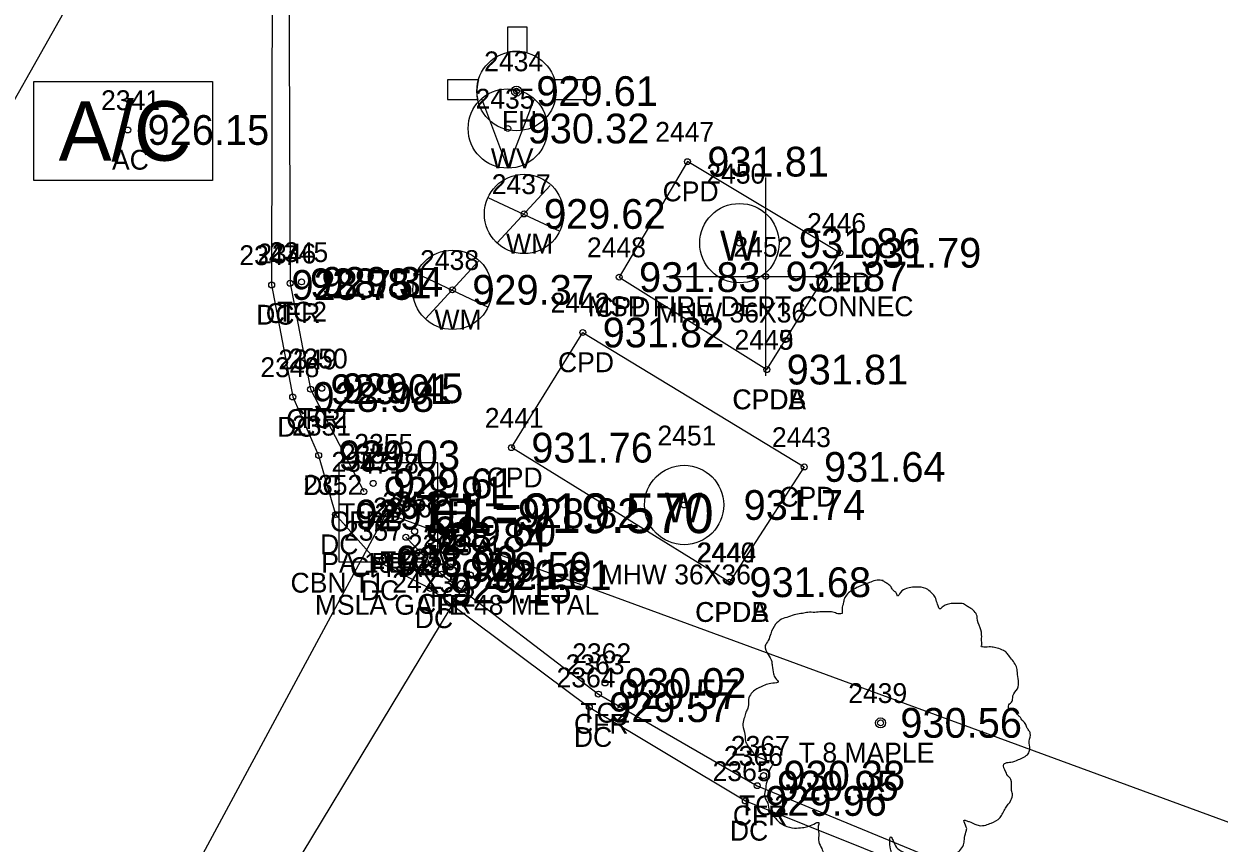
# Model space of a CAD drawing. Extents: x 1575382 to 1578175, y 1099175 to 1101955.
# Drawn here: x 1576768.2 to 1576828.4, y 1100126.4 to 1100167.7 of the extents above; entities that cross this region are included whole.
import ezdxf

# ---------------------------------------------------------------- set-up
doc = ezdxf.new("R2010")
doc.units = 0
for name, color, linetype in [('RD_EX_BldgApp', 7, 'Continuous'), ('RD_EX_BldgApp_txCode', 7, 'Continuous'), ('RD_EX_Conc', 7, 'Continuous'), ('RD_EX_Conc_txCode', 7, 'Continuous'), ('RD_EX_DR_Inlet', 7, 'Continuous'), ('RD_EX_DR_Inlet_txCode', 7, 'Continuous'), ('RD_EX_DR_Pipe', 7, 'Continuous'), ('RD_EX_DR_Pipe_txCode', 7, 'Continuous'), ('RD_EX_Misc', 7, 'Continuous'), ('RD_EX_Misc_txCode', 7, 'Continuous'), ('RD_EX_Road', 7, 'Continuous'), ('RD_EX_SU_H2O', 7, 'Continuous'), ('RD_EX_TX_BldgApp_ELEV', 7, 'Continuous'), ('RD_EX_TX_Conc_ELEV', 7, 'Continuous'), ('RD_EX_TX_DR_Inlet_ELEV', 7, 'Continuous'), ('RD_EX_TX_Misc_ELEV', 7, 'Continuous'), ('RD_EX_TX_UT_ELEV', 7, 'Continuous'), ('RD_EX_TX_VEG_ELEV', 7, 'Continuous'), ('RD_EX_UT', 7, 'Continuous'), ('RD_EX_UT_txCode', 7, 'Continuous'), ('RD_EX_VEG', 7, 'Continuous'), ('RD_EX_VEG_txCode', 7, 'Continuous'), ('RD_HC_Data', 7, 'Continuous'), ('RD_SMD_Locator', 7, 'Continuous'), ('RD_TX_Pipe_ElevEX', 7, 'Continuous')]:
    doc.layers.add(name, color=color, linetype=linetype)

msp = doc.modelspace()

# ---------------------------------------------------------------- linework, layer by layer
at = {"layer": 'RD_EX_BldgApp'}
msp.add_lwpolyline([(1576768.656, 1100159.831), (1576768.656, 1100164.831), (1576777.656, 1100164.831), (1576777.656, 1100159.831)], close=True, dxfattribs=at)
at = {"layer": 'RD_EX_Conc'}
for points in [[(1576785.777, 1100195.961), (1576786.17, 1100195.752), (1576783.397, 1100187.603), (1576781.942, 1100181.747), (1576781.056, 1100176.612), (1576780.677, 1100170.531), (1576780.648, 1100154.572), (1576781.71, 1100148.925), (1576783.019, 1100145.98), (1576783.874, 1100142.998), (1576785.927, 1100140.682), (1576788.648, 1100139.275), (1576796.673, 1100133.29), (1576804.546, 1100128.565), (1576819.43, 1100122.601)], [(1576782.012, 1100176.69), (1576781.508, 1100170.553), (1576781.58, 1100154.655), (1576782.614, 1100149.316), (1576785.295, 1100144.157)], [(1576805.627, 1100150.306), (1576809.311, 1100156.194), (1576801.625, 1100160.787), (1576798.181, 1100154.967), (1576805.627, 1100150.306)], [(1576803.749, 1100139.589), (1576792.746, 1100146.371), (1576796.345, 1100152.176), (1576807.513, 1100145.4), (1576803.749, 1100139.589)], [(1576787.42, 1100141.854), (1576789.211, 1100139.996), (1576797.129, 1100133.951), (1576805.141, 1100129.335), (1576819.688, 1100123.321)]]:
    msp.add_lwpolyline(points, dxfattribs=at)
at = {"layer": 'RD_EX_DR_Inlet'}
msp.add_line((1576789.035, 1100140.609), (1576789.035, 1100145.609), dxfattribs=at)
msp.add_lwpolyline([(1576789.035, 1100140.609), (1576789.035, 1100145.609), (1576784.035, 1100145.609), (1576784.035, 1100140.609)], close=True, dxfattribs=at)
at = {"layer": 'RD_EX_DR_Pipe'}
msp.add_lwpolyline([(1576756.712, 1100087.957), (1576786.445, 1100143.064), (1576786.445, 1100143.064), (1576927.309, 1100091.425)], dxfattribs=at)
at = {"layer": 'RD_EX_Misc'}
for p, q in [((1576805.573, 1100149.996), (1576805.573, 1100159.996)), ((1576800.573, 1100154.996), (1576810.573, 1100154.996)), ((1576790.668, 1100139.95), (1576773.845, 1100112.125))]:
    msp.add_line(p, q, dxfattribs=at)
at = {"layer": 'RD_EX_Road'}
msp.add_lwpolyline([(1576663.307, 1099979.534), (1576687.432, 1100021.526), (1576712.032, 1100065.104), (1576738.416, 1100112.144), (1576760.611, 1100151.412), (1576785.777, 1100195.961), (1576800.589, 1100221.872), (1576817.543, 1100252.084), (1576858.248, 1100324.631), (1576880.454, 1100364.005), (1576883.5, 1100369.448), (1576896.98, 1100397.709)], dxfattribs=at)
at = {"layer": 'RD_EX_SU_H2O'}
for centre in [(1576804.245, 1100156.678), (1576801.455, 1100143.482)]:
    msp.add_circle(centre, 2, dxfattribs=at)
at = {"layer": 'RD_EX_UT'}
for p, q in [((1576792.541, 1100167.563), (1576792.541, 1100166.289)), ((1576793.541, 1100167.563), (1576792.541, 1100167.563)), ((1576793.541, 1100166.266), (1576793.541, 1100167.563)), ((1576791.082, 1100164.915), (1576789.524, 1100164.915)), ((1576789.524, 1100164.915), (1576789.524, 1100163.915)), ((1576796.524, 1100164.915), (1576794.914, 1100164.915)), ((1576796.524, 1100163.915), (1576796.524, 1100164.915)), ((1576789.524, 1100163.915), (1576791.044, 1100163.915)), ((1576792.562, 1100160.465), (1576791.259, 1100163.948)), ((1576792.562, 1100160.465), (1576793.885, 1100163.911)), ((1576794.952, 1100163.915), (1576796.524, 1100163.915)), ((1576792.03, 1100156.693), (1576794.697, 1100159.589)), ((1576791.548, 1100158.988), (1576795.179, 1100157.275)), ((1576788.416, 1100152.868), (1576791.084, 1100155.764)), ((1576787.935, 1100155.163), (1576791.566, 1100153.45))]:
    msp.add_line(p, q, dxfattribs=at)
for centre, radius in [((1576792.998, 1100164.342), 2), ((1576792.562, 1100162.458), 2), ((1576792.998, 1100164.342), 0.25), ((1576793.382, 1100158.151), 2), ((1576789.768, 1100154.326), 2)]:
    msp.add_circle(centre, radius, dxfattribs=at)
for start, end in [(74.24553, 103.21276), (163.3387, 192.31502), (347.68498, 16.6613)]:
    msp.add_arc((1576792.998, 1100164.342), 2, start, end, dxfattribs=at)
at = {"layer": 'RD_EX_VEG'}
for centre, radius in [((1576811.362, 1100132.501), 0.25), ((1576811.35, 1100132.482), 0.0001)]:
    msp.add_circle(centre, radius, dxfattribs=at)
for points in [[(1576811.494, 1100139.669), (1576811.194, 1100139.694), (1576810.869, 1100139.594), (1576810.619, 1100139.494), (1576810.395, 1100139.419), (1576810.17, 1100139.319), (1576809.87, 1100139.144), (1576809.645, 1100138.944), (1576809.52, 1100138.694), (1576809.47, 1100138.469), (1576809.42, 1100138.194), (1576809.42, 1100138.019), (1576809.295, 1100137.994), (1576809.145, 1100138.019), (1576808.895, 1100138.094), (1576808.645, 1100138.094), (1576808.395, 1100138.094), (1576808.046, 1100138.069), (1576807.696, 1100138.069), (1576807.421, 1100138.019), (1576807.096, 1100137.969), (1576806.721, 1100137.844), (1576806.371, 1100137.719), (1576806.071, 1100137.469), (1576805.822, 1100136.995), (1576805.697, 1100136.645), (1576805.547, 1100136.395), (1576805.697, 1100135.945), (1576805.872, 1100135.595), (1576805.896, 1100135.395), (1576805.971, 1100134.971), (1576806.071, 1100134.746), (1576806.196, 1100134.546), (1576806.121, 1100134.521), (1576805.747, 1100134.471), (1576805.447, 1100134.371), (1576805.022, 1100134.146), (1576804.797, 1100133.921), (1576804.697, 1100133.596), (1576804.672, 1100133.246), (1576804.572, 1100133.046), (1576804.497, 1100132.772), (1576804.472, 1100132.697), (1576804.422, 1100132.372), (1576804.522, 1100131.922), (1576804.547, 1100131.572), (1576804.672, 1100131.347), (1576804.822, 1100131.172), (1576804.997, 1100130.922), (1576805.397, 1100130.697), (1576805.722, 1100130.597), (1576805.921, 1100130.573), (1576805.747, 1100130.073), (1576805.697, 1100129.723), (1576805.572, 1100129.323), (1576805.572, 1100129.248), (1576805.522, 1100128.773), (1576805.672, 1100128.448), (1576805.747, 1100128.074), (1576805.921, 1100127.849), (1576806.196, 1100127.549), (1576806.521, 1100127.324), (1576807.021, 1100127.199), (1576807.421, 1100127.224), (1576807.996, 1100127.399), (1576808.245, 1100127.474), (1576808.22, 1100127.299), (1576808.245, 1100126.924), (1576808.245, 1100126.499), (1576808.395, 1100126.174), (1576808.495, 1100125.9), (1576808.645, 1100125.65), (1576808.97, 1100125.425), (1576809.37, 1100125.35), (1576809.795, 1100125.2), (1576810.245, 1100125.125), (1576810.744, 1100125.1), (1576811.344, 1100125.25), (1576811.619, 1100125.375), (1576811.719, 1100125.55), (1576811.919, 1100125.925), (1576811.869, 1100126.149), (1576811.894, 1100126.749), (1576811.994, 1100126.574), (1576812.169, 1100126.224), (1576812.669, 1100125.925), (1576813.068, 1100125.75), (1576813.543, 1100125.6), (1576813.843, 1100125.525), (1576814.318, 1100125.6), (1576814.693, 1100125.675), (1576815.067, 1100125.8), (1576815.367, 1100126.074), (1576815.542, 1100126.349), (1576815.592, 1100126.624), (1576815.667, 1100126.999), (1576815.717, 1100127.174)], [(1576815.717, 1100127.174), (1576815.642, 1100127.349), (1576815.592, 1100127.599), (1576815.667, 1100127.574), (1576815.842, 1100127.524), (1576816.117, 1100127.399), (1576816.342, 1100127.324), (1576816.667, 1100127.349), (1576816.942, 1100127.449), (1576817.391, 1100127.724), (1576817.666, 1100128.199), (1576817.941, 1100128.598), (1576818.016, 1100128.923), (1576817.966, 1100129.148), (1576817.941, 1100129.648), (1576817.741, 1100129.898), (1576817.691, 1100130.023), (1576817.591, 1100130.423), (1576817.666, 1100130.473), (1576817.941, 1100130.523), (1576818.316, 1100130.647), (1576818.591, 1100130.772), (1576818.816, 1100130.947), (1576818.891, 1100131.172), (1576818.866, 1100131.572), (1576818.916, 1100131.972), (1576818.841, 1100132.122), (1576818.741, 1100132.272), (1576818.666, 1100132.472), (1576818.516, 1100132.622), (1576818.416, 1100132.772), (1576818.316, 1100132.871), (1576818.191, 1100133.021), (1576818.016, 1100133.146), (1576817.866, 1100133.196), (1576817.816, 1100133.346), (1576817.966, 1100133.546), (1576818.016, 1100133.646), (1576818.041, 1100133.871), (1576818.266, 1100134.221), (1576818.316, 1100134.621), (1576818.266, 1100135.046), (1576818.216, 1100135.32), (1576818.066, 1100135.595), (1576817.866, 1100135.845), (1576817.741, 1100136.02), (1576817.566, 1100136.145), (1576817.242, 1100136.27), (1576816.992, 1100136.32), (1576816.642, 1100136.32), (1576816.442, 1100136.37), (1576816.467, 1100136.42), (1576816.467, 1100136.57), (1576816.467, 1100136.845), (1576816.392, 1100137.295), (1576816.242, 1100137.794), (1576816.242, 1100137.819), (1576816.142, 1100138.069), (1576815.917, 1100138.269), (1576815.742, 1100138.369), (1576815.542, 1100138.494), (1576815.292, 1100138.519), (1576814.993, 1100138.519), (1576814.718, 1100138.469), (1576814.518, 1100138.369), (1576814.343, 1100138.244), (1576814.268, 1100138.394), (1576814.168, 1100138.694), (1576814.118, 1100138.844), (1576813.968, 1100139.019), (1576813.743, 1100139.219), (1576813.293, 1100139.344), (1576812.669, 1100139.269), (1576812.369, 1100139.069), (1576812.219, 1100138.894), (1576812.169, 1100139.019), (1576811.969, 1100139.219), (1576811.869, 1100139.394), (1576811.694, 1100139.519), (1576811.544, 1100139.619), (1576811.444, 1100139.669)]]:
    msp.add_spline(points, degree=3, dxfattribs=at)
at = {"layer": 'RD_SMD_Locator'}
for centre, radius in [((1576792.998, 1100164.342), 0.15), ((1576792.562, 1100162.458), 0.15), ((1576773.39, 1100162.383), 0.15), ((1576801.625, 1100160.787), 0.15), ((1576793.382, 1100158.151), 0.15), ((1576804.245, 1100156.678), 0.15), ((1576809.311, 1100156.194), 0.15), ((1576780.648, 1100154.572), 0.15), ((1576781.58, 1100154.655), 0.15), ((1576782.157, 1100154.726), 0.15), ((1576798.181, 1100154.967), 0.15), ((1576805.573, 1100154.996), 0.15), ((1576789.768, 1100154.326), 0.15), ((1576796.345, 1100152.176), 0.15), ((1576805.627, 1100150.306), 0.15), ((1576805.627, 1100150.306), 0.15), ((1576782.614, 1100149.316), 0.15), ((1576783.179, 1100149.364), 0.15), ((1576781.71, 1100148.925), 0.15), ((1576792.746, 1100146.371), 0.15), ((1576783.019, 1100145.98), 0.15), ((1576807.513, 1100145.4), 0.15), ((1576785.771, 1100144.572), 0.15), ((1576785.295, 1100144.157), 0.15), ((1576786.445, 1100143.064), 0.2), ((1576786.445, 1100143.064), 0.2), ((1576801.455, 1100143.482), 0.15), ((1576783.874, 1100142.998), 0.15), ((1576786.445, 1100143.064), 0.15), ((1576787.859, 1100142.151), 0.15), ((1576787.42, 1100141.854), 0.15), ((1576785.927, 1100140.682), 0.15), ((1576789.652, 1100140.36), 0.15), ((1576789.211, 1100139.996), 0.15), ((1576790.668, 1100139.95), 0.15), ((1576803.749, 1100139.589), 0.15), ((1576803.749, 1100139.589), 0.15), ((1576788.648, 1100139.275), 0.15), ((1576797.464, 1100134.51), 0.15), ((1576797.129, 1100133.951), 0.15), ((1576796.673, 1100133.29), 0.15), ((1576811.362, 1100132.501), 0.15), ((1576805.141, 1100129.335), 0.15), ((1576805.466, 1100129.841), 0.15), ((1576804.546, 1100128.565), 0.15)]:
    msp.add_circle(centre, radius, dxfattribs=at)

# ---------------------------------------------------------------- texts
at = {"layer": 'RD_EX_BldgApp'}
msp.add_text('A/C', height=3, dxfattribs=at).set_placement((1576769.902, 1100160.835))
at = {"layer": 'RD_EX_BldgApp_txCode'}
for s, p in [('2341', (1576772.044, 1100163.383)), ('AC', (1576772.595, 1100160.383))]:
    msp.add_text(s, height=1, dxfattribs=at).set_placement(p)
at = {"layer": 'RD_EX_Conc_txCode'}
for s, p in [('2447', (1576799.995, 1100161.787)), ('CPD', (1576800.373, 1100158.787)), ('2446', (1576807.658, 1100157.194)), ('2347', (1576779.018, 1100155.572)), ('2346', (1576779.926, 1100155.655)), ('2345', (1576780.527, 1100155.726)), ('2448', (1576796.551, 1100155.967)), ('CPD', (1576808.059, 1100154.194)), ('2442', (1576794.715, 1100153.176)), ('DC', (1576779.868, 1100152.572)), ('CFR', (1576780.351, 1100152.655)), ('TC2', (1576780.913, 1100152.726)), ('CPD', (1576796.929, 1100152.967)), ('2445', (1576803.997, 1100151.306)), ('2449', (1576803.997, 1100151.306)), ('2349', (1576780.984, 1100150.316)), ('2350', (1576781.51, 1100150.364)), ('CPD', (1576795.093, 1100150.176)), ('2348', (1576780.08, 1100149.925)), ('CPDA', (1576803.887, 1100148.306)), ('CPDB', (1576803.902, 1100148.306)), ('CFR', (1576781.386, 1100147.316)), ('TC2', (1576781.935, 1100147.364)), ('2441', (1576791.399, 1100147.371)), ('DC', (1576780.931, 1100146.925)), ('2351', (1576781.673, 1100146.98)), ('2443', (1576805.883, 1100146.4)), ('2354', (1576784.141, 1100145.572)), ('2353', (1576783.665, 1100145.157)), ('CPD', (1576791.494, 1100144.371)), ('2352', (1576782.244, 1100143.998)), ('DC', (1576782.24, 1100143.98)), ('2356', (1576785.766, 1100142.854)), ('2358', (1576786.229, 1100143.151)), ('CPD', (1576806.261, 1100143.4)), ('TC2B', (1576784.054, 1100142.572)), ('CFRB', (1576783.594, 1100142.157)), ('2357', (1576784.297, 1100141.682)), ('2361', (1576788.282, 1100141.36)), ('DC', (1576783.094, 1100140.998)), ('2360', (1576787.518, 1100140.996)), ('2440', (1576802.08, 1100140.589)), ('2444', (1576802.119, 1100140.589)), ('CFRA 18', (1576784.601, 1100139.854)), ('TC2A', (1576786.126, 1100140.151)), ('2359', (1576787.018, 1100140.275)), ('DC', (1576785.147, 1100138.682)), ('TC2', (1576788.408, 1100138.36)), ('CFR', (1576787.982, 1100137.996)), ('CPDA', (1576802.009, 1100137.589)), ('CPDB', (1576802.024, 1100137.589)), ('DC', (1576787.869, 1100137.275)), ('2362', (1576795.81, 1100135.51)), ('2363', (1576795.476, 1100134.951)), ('2364', (1576795.02, 1100134.29)), ('TC2', (1576796.22, 1100132.51)), ('CFR', (1576795.901, 1100131.951)), ('DC', (1576795.894, 1100131.29)), ('2367', (1576803.813, 1100130.841)), ('2366', (1576803.463, 1100130.335)), ('2365', (1576802.893, 1100129.565)), ('TC2', (1576804.222, 1100127.841)), ('CFR', (1576803.912, 1100127.335)), ('DC', (1576803.767, 1100126.565))]:
    msp.add_text(s, height=1, dxfattribs=at).set_placement(p)
at = {"layer": 'RD_EX_DR_Inlet_txCode'}
for s, p in [('2355', (1576784.815, 1100146.064)), ('CBN T1 24X36', (1576781.602, 1100139.064))]:
    msp.add_text(s, height=1, dxfattribs=at).set_placement(p)
at = {"layer": 'RD_EX_DR_Pipe_txCode'}
for s, p in [('4718', (1576785.098, 1100145.064)), ('4717', (1576785.098, 1100145.064)), ('PA 18 RC', (1576783.153, 1100140.064)), ('PB', (1576785.665, 1100140.064))]:
    msp.add_text(s, height=1, dxfattribs=at).set_placement(p)
at = {"layer": 'RD_EX_Misc_txCode'}
for s, p in [('2452', (1576803.943, 1100155.996)), ('MSP FIRE DEPT CONNEC', (1576796.604, 1100152.996)), ('2371', (1576789.281, 1100140.95)), ('MSLA GATE 48 METAL', (1576782.829, 1100137.95))]:
    msp.add_text(s, height=1, dxfattribs=at).set_placement(p)
at = {"layer": 'RD_EX_SU_H2O'}
for p in [(1576803.262, 1100155.802), (1576800.473, 1100142.606)]:
    msp.add_text('W', height=1.5, dxfattribs=at).set_placement(p)
at = {"layer": 'RD_EX_TX_BldgApp_ELEV'}
msp.add_text('926.15', height=1.5, dxfattribs=at).set_placement((1576774.39, 1100161.633))
at = {"layer": 'RD_EX_TX_Conc_ELEV'}
for s, p in [('931.81', (1576802.625, 1100160.037)), ('931.79', (1576810.311, 1100155.444)), ('928.75', (1576781.648, 1100153.822)), ('928.81', (1576782.58, 1100153.905)), ('929.34', (1576783.157, 1100153.976)), ('931.83', (1576799.181, 1100154.217)), ('931.82', (1576797.345, 1100151.426)), ('931.81', (1576806.627, 1100149.556)), ('931.81', (1576806.627, 1100149.556)), ('929.01', (1576783.614, 1100148.566)), ('929.45', (1576784.179, 1100148.614)), ('928.98', (1576782.71, 1100148.175)), ('931.76', (1576793.746, 1100145.621)), ('929.03', (1576784.019, 1100145.23)), ('931.64', (1576808.513, 1100144.65)), ('929.61', (1576786.771, 1100143.822)), ('928.91', (1576786.295, 1100143.407)), ('929.07', (1576784.874, 1100142.248)), ('929.60', (1576788.859, 1100141.401)), ('928.84', (1576788.42, 1100141.104)), ('928.99', (1576786.927, 1100139.932)), ('929.59', (1576790.652, 1100139.61)), ('929.11', (1576790.211, 1100139.246)), ('931.68', (1576804.749, 1100138.839)), ('931.68', (1576804.749, 1100138.839)), ('929.15', (1576789.648, 1100138.525)), ('930.02', (1576798.464, 1100133.76)), ('929.57', (1576798.129, 1100133.201)), ('929.57', (1576797.673, 1100132.54)), ('930.38', (1576806.466, 1100129.091)), ('929.95', (1576806.141, 1100128.585)), ('929.96', (1576805.546, 1100127.815))]:
    msp.add_text(s, height=1.5, dxfattribs=at).set_placement(p)
at = {"layer": 'RD_EX_TX_DR_Inlet_ELEV'}
msp.add_text('EL=928.82', height=1.5, dxfattribs=at).set_placement((1576789.445, 1100142.314))
at = {"layer": 'RD_EX_TX_Misc_ELEV'}
for s, p in [('931.87', (1576806.573, 1100154.246)), ('929.61', (1576791.668, 1100139.2))]:
    msp.add_text(s, height=1.5, dxfattribs=at).set_placement(p)
at = {"layer": 'RD_EX_TX_UT_ELEV'}
for s, p in [('929.61', (1576793.998, 1100163.592)), ('930.32', (1576793.562, 1100161.708)), ('929.62', (1576794.382, 1100157.401)), ('931.86', (1576807.245, 1100155.928)), ('929.37', (1576790.768, 1100153.576)), ('931.74', (1576804.455, 1100142.732))]:
    msp.add_text(s, height=1.5, dxfattribs=at).set_placement(p)
at = {"layer": 'RD_EX_TX_VEG_ELEV'}
msp.add_text('930.56', height=1.5, dxfattribs=at).set_placement((1576812.362, 1100131.751))
at = {"layer": 'RD_EX_UT_txCode'}
for s, p in [('2434', (1576791.368, 1100165.342)), ('2435', (1576790.932, 1100163.458)), ('FH', (1576792.266, 1100162.342)), ('WV', (1576791.704, 1100160.458)), ('2437', (1576791.752, 1100159.151)), ('2450', (1576802.575, 1100159.678)), ('WM', (1576792.476, 1100156.151)), ('2438', (1576788.138, 1100155.326)), ('MHW 36X36', (1576800.032, 1100152.678)), ('WM', (1576788.863, 1100152.326)), ('2451', (1576800.109, 1100146.482)), ('MHW 36X36', (1576797.243, 1100139.482))]:
    msp.add_text(s, height=1, dxfattribs=at).set_placement(p)
at = {"layer": 'RD_EX_VEG_txCode'}
for s, p in [('2439', (1576809.732, 1100133.501)), ('T 8 MAPLE', (1576807.24, 1100130.501))]:
    msp.add_text(s, height=1, dxfattribs=at).set_placement(p)
at = {"layer": 'RD_HC_Data'}
msp.add_text('N 29%%d 29\' 15" E', height=6, rotation=60.51249, dxfattribs=at).set_placement((1576749.154, 1100162.303))
at = {"layer": 'RD_TX_Pipe_ElevEX'}
msp.add_text('EL=919.570', height=2, dxfattribs=at).set_placement((1576788.445, 1100142.064))
msp.add_text('EL=919.570', height=2, dxfattribs=at).set_placement((1576788.445, 1100142.064))

doc.saveas('drawing.dxf')
